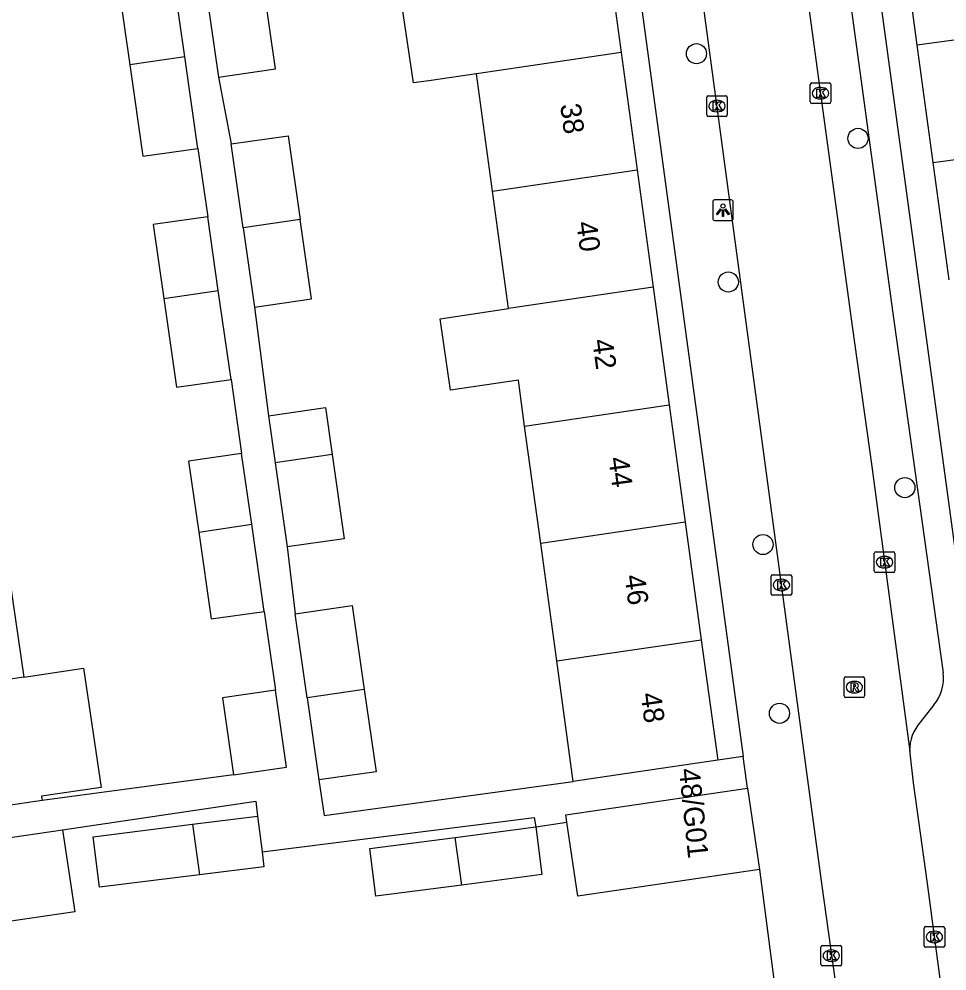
# Model space of a CAD drawing. Extents: x 159053 to 160041, y 380450 to 381422.
# Drawn here: x 159648.16 to 159693.25, y 381017.24 to 381063.48 of the extents above; entities that cross this region are included whole.
import ezdxf

# ---------------------------------------------------------------- set-up
doc = ezdxf.new("R2010")
doc.units = 0
for name, color, linetype in [('IMGEO_Boom', 7, 'Continuous'), ('IMGEO_Kolk', 7, 'Continuous'), ('IMGEO_Lichtpunt', 7, 'Continuous'), ('IMGEO_Muur', 7, 'Continuous'), ('IMGEO_Pand', 7, 'Continuous'), ('IMGEO_Pand_nummerreeks', 7, 'Continuous'), ('IMGEO_Rijbaan_lokaal_open', 7, 'Continuous'), ('IMGEO_Rioolput', 7, 'Continuous'), ('IMGEO_Voetpad_open', 7, 'Continuous')]:
    doc.layers.add(name, color=color, linetype=linetype)

msp = doc.modelspace()

# ---------------------------------------------------------------- linework, layer by layer
at = {"layer": 'IMGEO_Boom'}
for centre in [(159681.078, 381061.792), (159688.93, 381057.678), (159682.628, 381050.702), (159691.207, 381040.714), (159684.314, 381037.95), (159685.114, 381029.752)]:
    msp.add_circle(centre, 0.489, dxfattribs=at)
at = {"layer": 'IMGEO_Kolk'}
for p, q in [((159686.608, 381059.446), (159686.608, 381060.298)), ((159686.683, 381060.372), (159687.535, 381060.372)), ((159687.096, 381060.152), (159687.121, 381060.152)), ((159687.609, 381060.298), (159687.609, 381059.446)), ((159681.577, 381058.821), (159681.577, 381059.673)), ((159681.652, 381059.747), (159682.504, 381059.747)), ((159682.065, 381059.527), (159682.09, 381059.527)), ((159682.578, 381059.673), (159682.578, 381058.821)), ((159687.119, 381059.592), (159687.094, 381059.592)), ((159687.535, 381059.372), (159686.683, 381059.372)), ((159682.504, 381058.747), (159681.652, 381058.747)), ((159682.088, 381058.967), (159682.063, 381058.967)), ((159689.721, 381036.668), (159689.721, 381037.52)), ((159689.796, 381037.594), (159690.648, 381037.594)), ((159690.209, 381037.374), (159690.234, 381037.374)), ((159690.722, 381037.52), (159690.722, 381036.668)), ((159684.708, 381035.559), (159684.708, 381036.411)), ((159684.783, 381036.485), (159685.635, 381036.485)), ((159685.709, 381036.411), (159685.709, 381035.559)), ((159690.648, 381036.594), (159689.796, 381036.594)), ((159690.232, 381036.814), (159690.207, 381036.814)), ((159685.196, 381036.265), (159685.221, 381036.265)), ((159685.635, 381035.485), (159684.783, 381035.485)), ((159685.219, 381035.705), (159685.194, 381035.705)), ((159692.142, 381018.463), (159692.142, 381019.315)), ((159692.217, 381019.389), (159693.069, 381019.389)), ((159693.143, 381019.315), (159693.143, 381018.463)), ((159692.63, 381019.169), (159692.655, 381019.169)), ((159687.132, 381017.553), (159687.132, 381018.405)), ((159687.207, 381018.479), (159688.059, 381018.479)), ((159688.133, 381018.405), (159688.133, 381017.553)), ((159693.069, 381018.389), (159692.217, 381018.389)), ((159692.653, 381018.609), (159692.628, 381018.609)), ((159687.62, 381018.259), (159687.645, 381018.259)), ((159688.059, 381017.479), (159687.207, 381017.479)), ((159687.643, 381017.699), (159687.618, 381017.699))]:
    msp.add_line(p, q, dxfattribs=at)
for points in [[(159686.608, 381059.446), (159686.608, 381060.298)], [(159686.683, 381060.372), (159687.535, 381060.372)], [(159686.929, 381060.072), (159687.052, 381060.072), (159687.052, 381059.921), (159687.182, 381060.072), (159687.346, 381060.072), (159687.2, 381059.921), (159687.353, 381059.672), (159687.201, 381059.672), (159687.116, 381059.836), (159687.052, 381059.769), (159687.052, 381059.672), (159686.929, 381059.672), (159686.929, 381060.072)], [(159687.609, 381060.298), (159687.609, 381059.446)], [(159681.577, 381058.821), (159681.577, 381059.673)], [(159681.652, 381059.747), (159682.504, 381059.747)], [(159682.578, 381059.673), (159682.578, 381058.821)], [(159681.898, 381059.447), (159682.021, 381059.447), (159682.021, 381059.296), (159682.151, 381059.447), (159682.315, 381059.447), (159682.169, 381059.296), (159682.322, 381059.047), (159682.17, 381059.047), (159682.085, 381059.211), (159682.021, 381059.144), (159682.021, 381059.047), (159681.898, 381059.047), (159681.898, 381059.447)], [(159687.535, 381059.372), (159686.683, 381059.372)], [(159682.504, 381058.747), (159681.652, 381058.747)], [(159689.721, 381036.668), (159689.721, 381037.52)], [(159689.796, 381037.594), (159690.648, 381037.594)], [(159690.042, 381037.294), (159690.165, 381037.294), (159690.165, 381037.143), (159690.295, 381037.294), (159690.459, 381037.294), (159690.313, 381037.143), (159690.466, 381036.894), (159690.314, 381036.894), (159690.229, 381037.058), (159690.165, 381036.991), (159690.165, 381036.894), (159690.042, 381036.894), (159690.042, 381037.294)], [(159690.722, 381037.52), (159690.722, 381036.668)], [(159684.708, 381035.559), (159684.708, 381036.411)], [(159684.783, 381036.485), (159685.635, 381036.485)], [(159685.709, 381036.411), (159685.709, 381035.559)], [(159690.648, 381036.594), (159689.796, 381036.594)], [(159685.029, 381036.185), (159685.152, 381036.185), (159685.152, 381036.034), (159685.282, 381036.185), (159685.446, 381036.185), (159685.3, 381036.034), (159685.453, 381035.785), (159685.301, 381035.785), (159685.216, 381035.949), (159685.152, 381035.882), (159685.152, 381035.785), (159685.029, 381035.785), (159685.029, 381036.185)], [(159685.635, 381035.485), (159684.783, 381035.485)], [(159692.142, 381018.463), (159692.142, 381019.315)], [(159692.217, 381019.389), (159693.069, 381019.389)], [(159693.143, 381019.315), (159693.143, 381018.463)], [(159692.463, 381019.089), (159692.586, 381019.089), (159692.586, 381018.938), (159692.716, 381019.089), (159692.88, 381019.089), (159692.734, 381018.938), (159692.887, 381018.689), (159692.735, 381018.689), (159692.65, 381018.853), (159692.586, 381018.786), (159692.586, 381018.689), (159692.463, 381018.689), (159692.463, 381019.089)], [(159687.132, 381017.553), (159687.132, 381018.405)], [(159687.207, 381018.479), (159688.059, 381018.479)], [(159688.133, 381018.405), (159688.133, 381017.553)], [(159693.069, 381018.389), (159692.217, 381018.389)], [(159687.453, 381018.179), (159687.576, 381018.179), (159687.576, 381018.028), (159687.706, 381018.179), (159687.87, 381018.179), (159687.724, 381018.028), (159687.877, 381017.779), (159687.725, 381017.779), (159687.64, 381017.943), (159687.576, 381017.876), (159687.576, 381017.779), (159687.453, 381017.779), (159687.453, 381018.179)], [(159688.059, 381017.479), (159687.207, 381017.479)]]:
    msp.add_lwpolyline(points, dxfattribs=at)
for centre, start, end in [((159686.685, 381060.296), 91.552, 178.448), ((159686.685, 381060.296), 91.552, 178.448), ((159687.533, 381060.296), 1.552, 88.448), ((159687.533, 381060.296), 1.552, 88.448), ((159681.654, 381059.671), 91.552, 178.448), ((159681.654, 381059.671), 91.552, 178.448), ((159682.502, 381059.671), 1.552, 88.448), ((159682.502, 381059.671), 1.552, 88.448), ((159686.685, 381059.448), 181.552, 268.448), ((159686.685, 381059.448), 181.552, 268.448), ((159687.533, 381059.448), 271.552, 358.448), ((159687.533, 381059.448), 271.552, 358.448), ((159681.654, 381058.823), 181.552, 268.448), ((159681.654, 381058.823), 181.552, 268.448), ((159682.502, 381058.823), 271.552, 358.448), ((159682.502, 381058.823), 271.552, 358.448), ((159689.798, 381037.518), 91.552, 178.448), ((159689.798, 381037.518), 91.552, 178.448), ((159690.646, 381037.518), 1.552, 88.448), ((159690.646, 381037.518), 1.552, 88.448), ((159684.785, 381036.409), 91.552, 178.448), ((159684.785, 381036.409), 91.552, 178.448), ((159685.633, 381036.409), 1.552, 88.448), ((159685.633, 381036.409), 1.552, 88.448), ((159689.798, 381036.67), 181.552, 268.448), ((159689.798, 381036.67), 181.552, 268.448), ((159690.646, 381036.67), 271.552, 358.448), ((159690.646, 381036.67), 271.552, 358.448), ((159684.785, 381035.561), 181.552, 268.448), ((159684.785, 381035.561), 181.552, 268.448), ((159685.633, 381035.561), 271.552, 358.448), ((159685.633, 381035.561), 271.552, 358.448), ((159692.219, 381019.313), 91.552, 178.448), ((159692.219, 381019.313), 91.552, 178.448), ((159693.067, 381019.313), 1.552, 88.448), ((159693.067, 381019.313), 1.552, 88.448), ((159687.209, 381018.403), 91.552, 178.448), ((159687.209, 381018.403), 91.552, 178.448), ((159688.057, 381018.403), 1.552, 88.448), ((159688.057, 381018.403), 1.552, 88.448), ((159692.219, 381018.465), 181.552, 268.448), ((159692.219, 381018.465), 181.552, 268.448), ((159693.067, 381018.465), 271.552, 358.448), ((159693.067, 381018.465), 271.552, 358.448), ((159687.209, 381017.555), 181.552, 268.448), ((159687.209, 381017.555), 181.552, 268.448), ((159688.057, 381017.555), 271.552, 358.448), ((159688.057, 381017.555), 271.552, 358.448)]:
    msp.add_arc(centre, 0.0765, start, end, dxfattribs=at)
for centre, major_axis, ratio, start_param, end_param in [((159687.095, 381059.872), (-0.387, 0.002), 0.722429, 4.712389, 7.853982), ((159687.12, 381059.872), (-0.39, 0.002), 0.717154, 1.570796, 4.712389), ((159682.064, 381059.247), (-0.387, 0.002), 0.722429, 4.712389, 7.853982), ((159682.089, 381059.247), (-0.39, 0.002), 0.717154, 1.570796, 4.712389), ((159690.208, 381037.094), (-0.387, 0.002), 0.722429, 4.712389, 7.853982), ((159690.233, 381037.094), (-0.39, 0.002), 0.717154, 1.570796, 4.712389), ((159685.195, 381035.985), (-0.387, 0.002), 0.722429, 4.712389, 7.853982), ((159685.22, 381035.985), (-0.39, 0.002), 0.717154, 1.570796, 4.712389), ((159692.629, 381018.889), (-0.387, 0.002), 0.722429, 4.712389, 7.853982), ((159692.654, 381018.889), (-0.39, 0.002), 0.717154, 1.570796, 4.712389), ((159687.619, 381017.979), (-0.387, 0.002), 0.722429, 4.712389, 7.853982), ((159687.644, 381017.979), (-0.39, 0.002), 0.717154, 1.570796, 4.712389)]:
    msp.add_ellipse(centre, major_axis=major_axis, ratio=ratio, start_param=start_param, end_param=end_param, dxfattribs=at)
at = {"layer": 'IMGEO_Lichtpunt'}
for p, q in [((159681.87, 381054.595), (159681.87, 381053.788)), ((159681.87, 381054.595), (159681.87, 381053.788)), ((159682.772, 381054.69), (159681.964, 381054.69)), ((159682.772, 381054.69), (159681.964, 381054.69)), ((159682.866, 381053.788), (159682.866, 381054.595)), ((159682.866, 381053.788), (159682.866, 381054.595)), ((159681.964, 381053.694), (159682.772, 381053.694)), ((159681.964, 381053.694), (159682.772, 381053.694))]:
    msp.add_line(p, q, dxfattribs=at)
for points in [[(159682.244, 381054.259), (159682.283, 381054.231), (159682.095, 381053.969), (159682.057, 381053.996), (159682.244, 381054.259)], [(159682.346, 381054.211), (159682.393, 381054.211), (159682.393, 381053.889), (159682.346, 381053.889), (159682.346, 381054.211)], [(159682.456, 381054.231), (159682.494, 381054.258), (159682.681, 381053.996), (159682.642, 381053.968), (159682.456, 381054.231)]]:
    msp.add_lwpolyline(points, dxfattribs=at)
msp.add_circle((159682.369, 381054.393), 0.0994, dxfattribs=at)
for centre, start, end in [((159681.964, 381054.595), 90, 180), ((159681.964, 381054.595), 90, 180), ((159682.772, 381054.595), 0, 90), ((159682.772, 381054.595), 0, 90), ((159681.964, 381053.788), 180, 270), ((159681.964, 381053.788), 180, 270), ((159682.772, 381053.788), 270, 0), ((159682.772, 381053.788), 270, 360)]:
    msp.add_arc(centre, 0.0946, start, end, dxfattribs=at)
at = {"layer": 'IMGEO_Muur'}
msp.add_lwpolyline([(159684.14, 381022.17), (159685.656, 381010.607)], dxfattribs=at)
at = {"layer": 'IMGEO_Pand'}
for points in [[(159691.812, 381062.208), (159691.037, 381067.91)], [(159676.639, 381067.56), (159677.418, 381061.855)], [(159670.395, 381060.82), (159668.069, 381060.478), (159667.324, 381060.369), (159666.486, 381066.065), (159667.23, 381066.175), (159669.616, 381066.526)], [(159655.672, 381065.485), (159652.999, 381065.093), (159653.549, 381061.248)], [(159656.222, 381061.64), (159655.672, 381065.485)], [(159657.853, 381060.658), (159660.63, 381061.055), (159660.048, 381065.116)], [(159657.273, 381064.707), (159657.853, 381060.658)], [(159698.826, 381063.158), (159691.812, 381062.208)], [(159677.418, 381061.855), (159670.395, 381060.82)], [(159677.418, 381061.855), (159678.197, 381056.149)], [(159692.588, 381056.506), (159691.812, 381062.208)], [(159656.222, 381061.64), (159653.549, 381061.248)], [(159656.858, 381057.193), (159656.222, 381061.64)], [(159653.549, 381061.248), (159654.184, 381056.81), (159656.858, 381057.193)], [(159671.175, 381055.114), (159670.395, 381060.82)], [(159658.467, 381057.411), (159661.243, 381057.808), (159661.826, 381053.735)], [(159659.051, 381053.326), (159658.467, 381057.411)], [(159692.588, 381056.506), (159699.601, 381057.456)], [(159693.363, 381050.805), (159692.588, 381056.506)], [(159671.175, 381055.114), (159678.197, 381056.149)], [(159678.197, 381056.149), (159678.976, 381050.444)], [(159671.953, 381049.41), (159671.175, 381055.114)], [(159657.333, 381053.873), (159654.68, 381053.494), (159655.195, 381049.898)], [(159657.846, 381050.287), (159657.333, 381053.873)], [(159661.826, 381053.735), (159659.051, 381053.326)], [(159659.601, 381049.482), (159662.378, 381049.879), (159661.826, 381053.735)], [(159659.051, 381053.326), (159659.601, 381049.482)], [(159655.195, 381049.898), (159657.846, 381050.287)], [(159658.464, 381045.97), (159657.846, 381050.287)], [(159678.976, 381050.444), (159671.953, 381049.41)], [(159678.976, 381050.444), (159679.755, 381044.738)], [(159655.195, 381049.898), (159655.811, 381045.591), (159658.464, 381045.97)], [(159672.733, 381043.704), (159672.428, 381045.933), (159669.134, 381045.448), (159668.622, 381048.92), (159671.953, 381049.41)], [(159672.733, 381043.704), (159679.755, 381044.738)], [(159679.755, 381044.738), (159680.534, 381039.033)], [(159660.281, 381044.208), (159663.057, 381044.605), (159663.383, 381042.327)], [(159660.281, 381044.208), (159660.608, 381041.919)], [(159673.512, 381037.999), (159672.733, 381043.704)], [(159658.979, 381042.37), (159656.405, 381042.002), (159656.898, 381038.558)], [(159659.47, 381038.935), (159658.979, 381042.37)], [(159663.383, 381042.327), (159660.608, 381041.919)], [(159660.608, 381041.919), (159661.193, 381037.834)], [(159663.383, 381042.327), (159663.97, 381038.231), (159661.193, 381037.834)], [(159656.898, 381038.558), (159659.47, 381038.935)], [(159660.076, 381034.705), (159659.47, 381038.935)], [(159680.534, 381039.033), (159673.512, 381037.999)], [(159680.534, 381039.033), (159681.313, 381033.327)], [(159656.898, 381038.558), (159657.503, 381034.336), (159660.076, 381034.705)], [(159674.291, 381032.293), (159673.512, 381037.999)], [(159647.57, 381037.189), (159648.403, 381031.515)], [(159661.583, 381034.589), (159664.359, 381034.986), (159664.941, 381030.916)], [(159662.166, 381030.508), (159661.583, 381034.589)], [(159674.291, 381032.293), (159681.313, 381033.327)], [(159681.313, 381033.327), (159682.113, 381027.469)], [(159675.09, 381026.439), (159674.291, 381032.293)], [(159648.403, 381031.515), (159651.303, 381031.941), (159652.152, 381026.148), (159649.252, 381025.723), (159649.283, 381025.515)], [(159648.403, 381031.515), (159641.368, 381030.483)], [(159660.623, 381030.877), (159658.05, 381030.509), (159658.587, 381026.762)], [(159658.587, 381026.762), (159661.16, 381027.131), (159660.623, 381030.877)], [(159664.941, 381030.916), (159662.166, 381030.508)], [(159664.941, 381030.916), (159665.514, 381026.917), (159662.737, 381026.52)], [(159662.166, 381030.508), (159662.737, 381026.52)], [(159682.113, 381027.469), (159677.166, 381026.743), (159675.09, 381026.439)], [(159674.79, 381024.46), (159674.737, 381024.821), (159683.561, 381026.116)], [(159683.561, 381026.116), (159684.14, 381022.17)], [(159649.283, 381025.515), (159647.196, 381025.209), (159642.248, 381024.483)], [(159656.929, 381021.909), (159652.074, 381021.3), (159651.766, 381023.76), (159656.586, 381024.365)], [(159656.586, 381024.365), (159659.755, 381024.762)], [(159656.586, 381024.365), (159656.929, 381021.909)], [(159659.755, 381024.762), (159659.973, 381023.028)], [(159684.14, 381022.17), (159675.316, 381020.875), (159674.79, 381024.46)], [(159640.972, 381022.733), (159650.284, 381024.1)], [(159650.284, 381024.1), (159650.869, 381020.114), (159641.557, 381018.748)], [(159669.353, 381023.726), (159673.269, 381024.237)], [(159673.269, 381024.237), (159673.572, 381021.916), (159669.677, 381021.408)], [(159669.677, 381021.408), (159665.507, 381020.864), (159665.204, 381023.185), (159669.353, 381023.726)], [(159669.677, 381021.408), (159669.353, 381023.726)], [(159659.973, 381023.028), (159660.064, 381022.302), (159656.929, 381021.909)]]:
    msp.add_lwpolyline(points, dxfattribs=at)
at = {"layer": 'IMGEO_Rijbaan_lokaal_open'}
for points in [[(159683.492, 381086.37), (159688.653, 381048.555), (159689.604, 381041.734), (159691.441, 381027.917)], [(159689.262, 381006.55), (159688.989, 381008.512), (159687.185, 381021.364), (159686.517, 381026.277), (159678.493, 381085.883)], [(159691.441, 381027.917), (159691.446, 381027.813), (159691.614, 381026.377), (159692.295, 381021.493), (159694.287, 381006.515), (159694.531, 381005.393), (159695.018, 381001.889)]]:
    msp.add_lwpolyline(points, dxfattribs=at)
at = {"layer": 'IMGEO_Rioolput'}
for p, q in [((159688.252, 381030.595), (159688.252, 381031.447)), ((159688.327, 381031.521), (159689.179, 381031.521)), ((159688.74, 381031.301), (159688.765, 381031.301)), ((159689.253, 381031.447), (159689.253, 381030.595)), ((159689.179, 381030.521), (159688.327, 381030.521)), ((159688.763, 381030.741), (159688.738, 381030.741))]:
    msp.add_line(p, q, dxfattribs=at)
for points in [[(159688.252, 381030.595), (159688.252, 381031.447)], [(159688.327, 381031.521), (159689.179, 381031.521)], [(159689.253, 381031.447), (159689.253, 381030.595)], [(159688.841, 381031.219), (159688.589, 381031.221), (159688.589, 381030.821)], [(159688.589, 381030.821), (159688.713, 381030.821), (159688.713, 381030.983), (159688.724, 381030.983)], [(159688.767, 381031.14), (159688.713, 381031.14), (159688.713, 381031.059)], [(159688.713, 381031.059), (159688.765, 381031.059)], [(159688.771, 381030.954), (159688.842, 381030.821), (159688.982, 381030.821), (159688.917, 381030.947)], [(159689.179, 381030.521), (159688.327, 381030.521)]]:
    msp.add_lwpolyline(points, dxfattribs=at)
for centre, radius, start, end in [((159688.329, 381031.445), 0.0765, 91.552, 178.448), ((159688.329, 381031.445), 0.0765, 91.552, 178.448), ((159689.177, 381031.445), 0.0765, 1.552, 88.448), ((159689.177, 381031.445), 0.0765, 1.552, 88.448), ((159688.723, 381030.93), 0.0533, 26.0293, 88.6989), ((159688.749, 381031.248), 0.19, 274.7715, 282.9687), ((159688.773, 381031.044), 0.0964, 77.0061, 93.1865), ((159688.787, 381031.101), 0.0378, 276.6634, 79.6772), ((159688.84, 381031.109), 0.109, 350.3612, 89.416), ((159688.838, 381031.109), 0.112, 277.5842, 350.9817), ((159688.822, 381030.894), 0.108, 29.5134, 73.7905), ((159688.329, 381030.597), 0.0765, 181.552, 268.448), ((159688.329, 381030.597), 0.0765, 181.552, 268.448), ((159689.177, 381030.597), 0.0765, 271.552, 358.448), ((159689.177, 381030.597), 0.0765, 271.552, 358.448)]:
    msp.add_arc(centre, radius, start, end, dxfattribs=at)
for centre, major_axis, ratio, start_param, end_param in [((159688.739, 381031.021), (-0.387, 0.002), 0.722429, 4.712389, 7.853982), ((159688.764, 381031.021), (-0.39, 0.002), 0.717154, 1.570796, 4.712389)]:
    msp.add_ellipse(centre, major_axis=major_axis, ratio=ratio, start_param=start_param, end_param=end_param, dxfattribs=at)
at = {"layer": 'IMGEO_Voetpad_open'}
for points in [[(159668.05, 381130.466), (159669.393, 381130.571), (159683.353, 381027.651)], [(159681.977, 381130.689), (159681.022, 381130.534), (159695.018, 381027.623)], [(159679.729, 381129.583), (159684.168, 381096.521), (159690.677, 381048.834), (159693.064, 381031.721)], [(159657.853, 381060.658), (159658.467, 381057.411)], [(159656.858, 381057.193), (159657.333, 381053.873)], [(159659.601, 381049.482), (159660.281, 381044.208)], [(159658.464, 381045.97), (159658.979, 381042.37)], [(159661.193, 381037.834), (159661.583, 381034.589)], [(159660.076, 381034.705), (159660.623, 381030.877)], [(159692.621, 381030.165), (159691.967, 381029.33)], [(159683.353, 381027.651), (159682.113, 381027.469)], [(159683.561, 381026.116), (159683.353, 381027.651)], [(159658.587, 381026.762), (159649.283, 381025.515)], [(159662.737, 381026.52), (159662.985, 381024.787), (159675.09, 381026.439)], [(159650.284, 381024.1), (159659.665, 381025.477), (159659.755, 381024.762)], [(159659.973, 381023.028), (159673.202, 381024.69), (159673.269, 381024.237)], [(159673.269, 381024.237), (159674.79, 381024.46)], [(159684.14, 381022.17), (159685.656, 381010.607), (159687.308, 380998.005)]]:
    msp.add_lwpolyline(points, dxfattribs=at)
for centre, radius, start, end in [((159691.061, 381031.45), 2.022, 320.5226, 7.6937), ((159693.484, 381027.961), 2.044, 137.9336, 181.23)]:
    msp.add_arc(centre, radius, start, end, dxfattribs=at)

# ---------------------------------------------------------------- texts
at = {"layer": 'IMGEO_Pand_nummerreeks'}
for s, rotation, p in [('38', 277.775, (159674.455, 381059.312)), ('40', 277.775, (159675.236, 381053.59)), ('42', 277.7748, (159676.017, 381047.874)), ('44', 277.775, (159676.797, 381042.149)), ('46', 277.775, (159677.579, 381036.427)), ('48', 277.775, (159678.361, 381030.702)), ('48/G01', 275.8554, (159680.232, 381027.04))]:
    msp.add_text(s, height=1, rotation=rotation, dxfattribs=at).set_placement(p)

doc.saveas('drawing.dxf')
